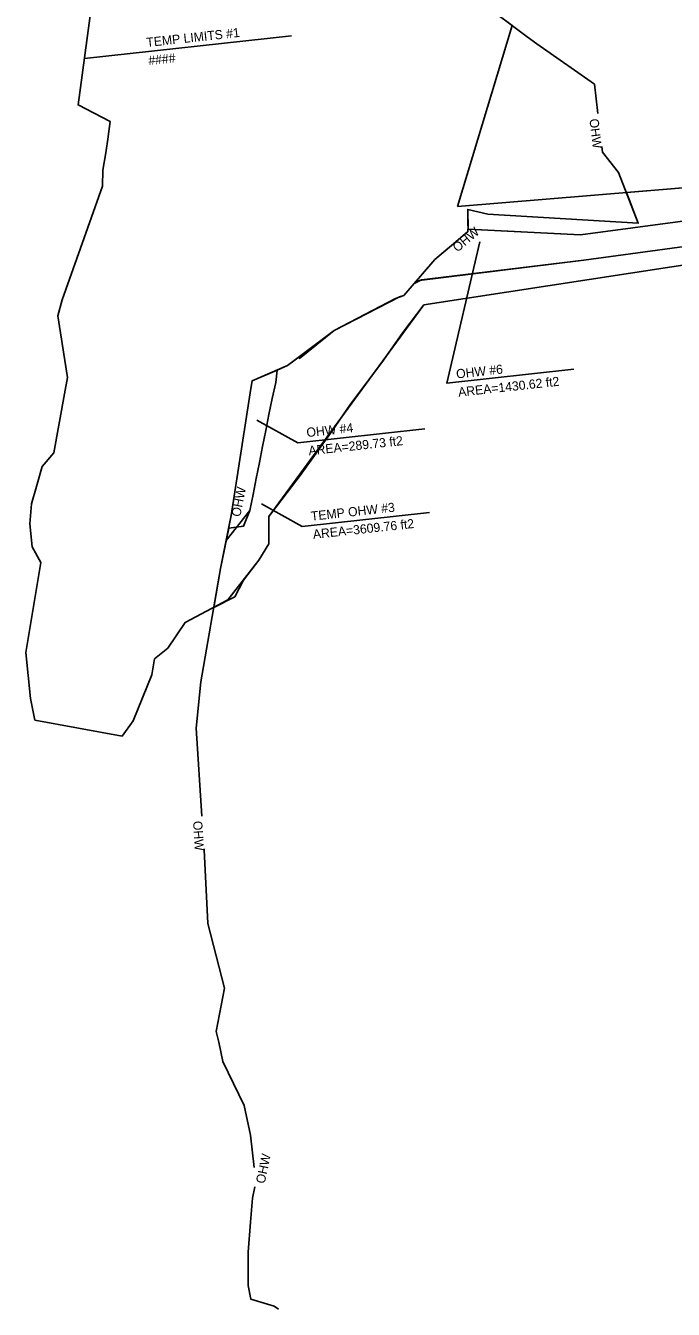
# Model space of a CAD drawing. Extents: x 1509537 to 1510685, y 401169 to 402194.
# Drawn here: x 1509734.7 to 1509932.9, y 401169.2 to 401562.2 of the extents above; entities that cross this region are included whole.
import ezdxf

# ---------------------------------------------------------------- set-up
doc = ezdxf.new("R2010")
doc.units = 0
for name, color, linetype in [('LAWE', 7, 'Continuous'), ('LAWE_P', 7, 'Continuous'), ('LAWE_P_T', 7, 'Continuous'), ('Level 6', 7, 'Continuous'), ('Level 9', 7, 'Continuous')]:
    doc.layers.add(name, color=color, linetype=linetype)

msp = doc.modelspace()

# ---------------------------------------------------------------- linework, layer by layer
at = {"layer": 'LAWE'}
for points in [[(1509909.8, 401535.31), (1509908.75, 401544.3), (1509891.05, 401556.7), (1509888.15, 401558.82), (1509873.96, 401569.39)], [(1509870.01, 401500.99), (1509869.96, 401505.96), (1509876.07, 401504.54), (1509922.14, 401501.76), (1509916.13, 401517.28), (1509911.17, 401523.54), (1509910.97, 401525.26)], [(1509798.91, 401420.87), (1509803.17, 401448.44), (1509803.56, 401451.18), (1509803.99, 401453.51), (1509814.78, 401458.16), (1509829.08, 401468.94), (1509847.87, 401478.69), (1509850.37, 401479.63), (1509859.92, 401490.6), (1509863.9, 401493.98)], [(1509788.58, 401320.23), (1509786.81, 401347.16), (1509788.24, 401361.35), (1509794.34, 401396.07), (1509797.3, 401410.87)], [(1509804.58, 401212.58), (1509803.51, 401222.5), (1509801.55, 401231.55), (1509794.98, 401245.1), (1509793.76, 401250.98), (1509793, 401254.21), (1509795.55, 401267.57), (1509790.47, 401287.33), (1509789.26, 401309.93), (1509789.25, 401310.14)], [(1509812.05, 401169.19), (1509810.71, 401170.16), (1509803.59, 401172.29), (1509802.78, 401176.52), (1509802.79, 401186.66), (1509803.48, 401195.88), (1509804.04, 401203.26), (1509804.78, 401206.73)]]:
    msp.add_lwpolyline(points, dxfattribs=at)
at = {"layer": 'LAWE_P'}
for points in [[(1509905.49, 401490.46), (1509955.04, 401497.19), (1510004.67, 401503.29), (1510014.27, 401505.12), (1510012.96, 401514.79), (1510003.27, 401513.6), (1509954, 401504.87), (1509904.45, 401498.18)], [(1509904.45, 401498.18), (1509870.02, 401499.95), (1509870.03, 401499.17), (1509864.97, 401494.89), (1509859.92, 401490.6), (1509854.28, 401484.13), (1509905.49, 401490.46)], [(1509811.59, 401456.79), (1509803.99, 401453.51), (1509803.56, 401451.18), (1509803.17, 401448.44), (1509797.57, 401412.24), (1509796.03, 401404.55)], [(1509796.03, 401404.55), (1509803.3, 401413.74), (1509804.29, 401418.65), (1509805.22, 401423.56), (1509806.18, 401428.47), (1509807.17, 401433.37), (1509808.2, 401438.26), (1509809.04, 401443.19), (1509810.14, 401448.07), (1509811.18, 401452.97), (1509811.59, 401456.79)]]:
    msp.add_lwpolyline(points, dxfattribs=at)
at = {"layer": 'LAWE_P_T'}
msp.add_line((1509752.66, 401552.21), (1509816.01, 401559.12), dxfattribs=at)
for points in [[(1509873.66, 401496.05), (1509863.55, 401452.78), (1509902.43, 401457.02)], [(1509805.44, 401441.45), (1509817.97, 401434.54), (1509856.85, 401438.78)], [(1509806.8, 401415.84), (1509819.32, 401408.93), (1509858.2, 401413.17)]]:
    msp.add_lwpolyline(points, dxfattribs=at)
at = {"layer": 'Level 6'}
msp.add_line((1509792.24, 401384.13), (1509798.71, 401387.33), dxfattribs=at)
for points in [[(1510032.06, 401520.51), (1509918.51, 401511.14), (1509922.14, 401501.76), (1509876.07, 401504.54), (1509869.96, 401505.96), (1509870.07, 401499.97), (1509904.45, 401498.18), (1509954, 401504.87)], [(1509798.71, 401387.33), (1509801.31, 401392.47), (1509806.06, 401398.55), (1509809.1, 401403.54), (1509809.07, 401412), (1509818.71, 401424.51), (1509828.48, 401438.13), (1509833.85, 401445.99), (1509844.2, 401459.8), (1509850.14, 401468.24), (1509856.53, 401476.73), (1510020.93, 401501.99)], [(1509955.04, 401497.19), (1509905.49, 401490.46), (1509855.85, 401484.44), (1509853.55, 401483.28), (1509850.37, 401479.63), (1509849.12, 401479.16), (1509829.08, 401468.94), (1509818.46, 401460.35), (1509818.66, 401461.09)], [(1509818.66, 401461.09), (1509814.78, 401458.16), (1509811.59, 401456.79)], [(1509811.59, 401456.79), (1509811.18, 401452.97), (1509810.14, 401448.07), (1509809.04, 401443.19), (1509808.2, 401438.26), (1509807.17, 401433.37), (1509806.18, 401428.47), (1509805.22, 401423.56), (1509804.29, 401418.65), (1509803.3, 401413.74), (1509801.37, 401409.02), (1509796.8, 401408.39)], [(1509796.8, 401408.39), (1509794.34, 401396.07), (1509792.24, 401384.13)]]:
    msp.add_lwpolyline(points, dxfattribs=at)
at = {"layer": 'Level 9'}
for p, q in [((1509883.57, 401562.24), (1509875.57, 401568.19)), ((1509866.77, 401506.88), (1509883.57, 401562.24)), ((1509736.15, 401356.22), (1509737.45, 401349.55)), ((1509737.45, 401349.55), (1509764.23, 401344.65)), ((1509764.23, 401344.65), (1509767.58, 401349.35))]:
    msp.add_line(p, q, dxfattribs=at)
for points in [[(1509754.87, 401568.33), (1509750.72, 401537.98), (1509760.49, 401532.85), (1509759.9, 401528.35), (1509759.88, 401528.18), (1509759.18, 401523.29), (1509758.34, 401518.04), (1509758.16, 401513.05), (1509745.86, 401478.25), (1509744.5, 401473.43), (1509747.44, 401454.46), (1509746.54, 401449.53), (1509743.29, 401431.45), (1509739.72, 401427.29), (1509738, 401421.18), (1509736.5, 401415.82), (1509735.92, 401409.67), (1509736.71, 401402.69), (1509739.35, 401397.84), (1509735.52, 401375.23), (1509734.69, 401370.28), (1509736.15, 401356.22)], [(1509767.58, 401349.35), (1509773.28, 401363.45), (1509774.1, 401368.36), (1509778.17, 401371.6), (1509783.48, 401379.52), (1509796.56, 401386.39), (1509806.06, 401398.55), (1509809.1, 401403.54), (1509809.07, 401412), (1509856.53, 401476.73), (1510020.93, 401501.99), (1510032.06, 401520.51), (1509866.77, 401506.88)]]:
    msp.add_lwpolyline(points, dxfattribs=at)

# ---------------------------------------------------------------- texts
at = {"layer": 'LAWE'}
for rotation, p in [(276.6425, (1509907.18, 401533.6)), (40.282, (1509866.78, 401492.75)), (78.6959, (1509800.32, 401411.69)), (273.7616, (1509785.88, 401318.65)), (78.0796, (1509807.81, 401207.52))]:
    msp.add_text('OHW', height=2.8, rotation=rotation, dxfattribs=at).set_placement(p)
at = {"layer": 'LAWE_P_T'}
for s, p in [('TEMP LIMITS #1', (1509771.77, 401555.7)), ('####', (1509772.37, 401550.14)), ('OHW #6', (1509866.56, 401454.19)), ('AREA=1430.62 ft2', (1509867.17, 401448.63)), ('OHW #4', (1509820.76, 401436.25)), ('AREA=289.73 ft2', (1509821.36, 401430.69)), ('TEMP OHW #3', (1509822.11, 401410.64)), ('AREA=3609.76 ft2', (1509822.72, 401405.08))]:
    msp.add_text(s, height=2.8, rotation=6.2219, dxfattribs=at).set_placement(p)

doc.saveas('drawing.dxf')
